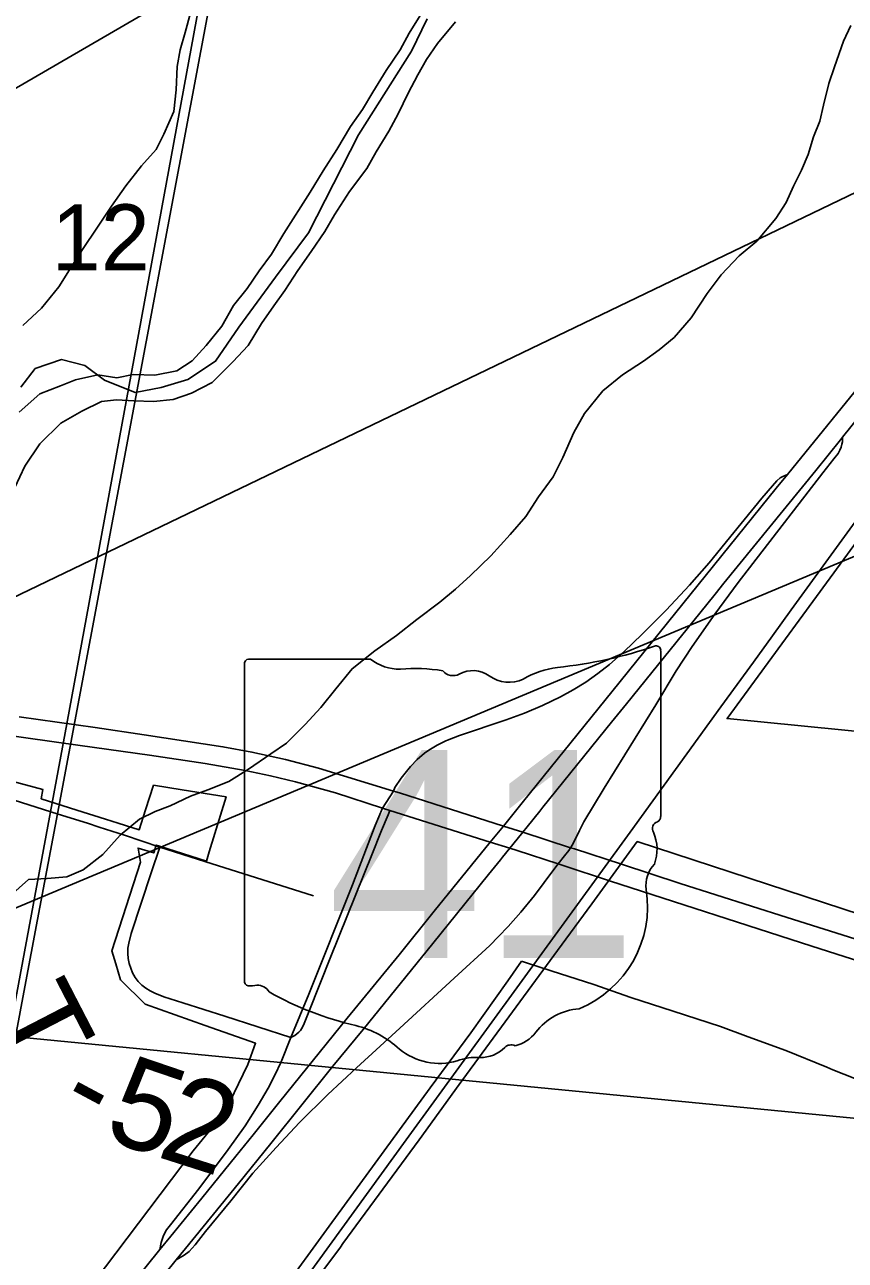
# Model space of a CAD drawing. Extents: x 0 to 34, y 0 to 22.
# Drawn here: x 7.664 to 8.184, y 18.991 to 19.774 of the extents above; entities that cross this region are included whole.
import ezdxf

# ---------------------------------------------------------------- set-up
doc = ezdxf.new("R2010")
doc.units = 0
for name, color, linetype in [('GM_X_City_Street', 7, 'Continuous'), ('GM_X_Interchange_Ramps', 7, 'Continuous'), ('GM_X_Major_River', 7, 'Continuous'), ('GM_X_Minor_River', 7, 'Continuous'), ('GM_X_Rail_Line', 7, 'Continuous'), ('GM_X_Section', 7, 'Continuous'), ('GM_X_Section_Text', 7, 'Continuous'), ('GM_X_State_Location', 7, 'Continuous'), ('GM_X_State_Route', 7, 'Continuous'), ('GM_X_State_Shield', 7, 'Continuous'), ('GM_X_Township_Road', 7, 'Continuous'), ('GM_X_Township_Road_Text', 7, 'Continuous'), ('GM_X_US_Route', 7, 'Continuous'), ('SC_Shading1', 7, 'Continuous'), ('SH_Text', 7, 'Continuous')]:
    doc.layers.add(name, color=color, linetype=linetype)

msp = doc.modelspace()

# ---------------------------------------------------------------- linework, layer by layer
at = {"layer": 'GM_X_City_Street'}
for points in [[(7.91919, 19.77751), (7.90941, 19.75708), (7.87575, 19.70401), (7.84421, 19.6418), (7.8231, 19.61391), (7.79992, 19.58224), (7.78521, 19.56057), (7.76768, 19.54907), (7.75073, 19.54398), (7.73433, 19.54078), (7.71492, 19.54851), (7.70248, 19.55793), (7.68758, 19.5617), (7.671, 19.55586), (7.66195, 19.54417)], [(7.66195, 19.54417), (7.671, 19.55586), (7.68758, 19.5617), (7.70248, 19.55793), (7.71492, 19.54851), (7.73433, 19.54078), (7.75073, 19.54398), (7.76768, 19.54907), (7.78521, 19.56057), (7.79992, 19.58224), (7.8231, 19.61391), (7.84421, 19.6418), (7.87575, 19.70401), (7.90941, 19.75708), (7.91919, 19.77751)]]:
    msp.add_lwpolyline(points, dxfattribs=at)
at = {"layer": 'GM_X_Interchange_Ramps'}
for points in [[(8.01008, 19.25236), (8.01161, 19.25468), (8.01578, 19.26328), (8.01862, 19.26879), (8.03147, 19.29009), (8.06414, 19.34298), (8.07694, 19.36431), (8.08715, 19.37993), (8.10146, 19.4003), (8.11626, 19.42031), (8.16997, 19.48977), (8.17692, 19.49875), (8.17957, 19.50218), (8.18071, 19.50412), (8.1816, 19.50621), (8.18205, 19.50793), (8.1823, 19.50954), (8.18237, 19.51088), (8.18237, 19.51241)], [(8.14754, 19.48879), (8.14463, 19.48758), (8.14282, 19.48663), (8.14072, 19.48482), (8.13806, 19.48157), (8.13129, 19.47375), (8.11356, 19.45208), (8.09783, 19.4328), (8.08553, 19.41876), (8.07065, 19.40286), (8.05534, 19.38737), (8.04407, 19.37664), (8.03472, 19.36843), (8.0274, 19.36266), (8.01976, 19.35731), (8.01183, 19.35241), (8.00364, 19.34793), (7.99243, 19.34253), (7.98099, 19.33766), (7.96934, 19.3333), (7.93984, 19.32342), (7.93211, 19.32039)], [(7.93211, 19.32039), (7.93115, 19.32001), (7.92555, 19.3173), (7.92023, 19.31411), (7.91769, 19.31232), (7.91296, 19.3083), (7.90867, 19.3038), (7.90284, 19.29651), (7.8989, 19.2905), (7.89798, 19.28825)], [(7.89798, 19.28825), (7.89093, 19.2774), (7.88638, 19.26634), (7.87191, 19.22875), (7.84439, 19.15966), (7.83296, 19.13208), (7.82669, 19.11668), (7.82282, 19.10823), (7.81856, 19.09996), (7.81231, 19.08926), (7.80388, 19.07626), (7.79316, 19.06106), (7.77454, 19.03628), (7.75678, 19.01354), (7.75424, 19.0102), (7.75217, 19.00659), (7.75075, 19.00233), (7.75003, 18.99775)], [(7.83296, 19.13208), (7.83541, 19.13341), (7.8379, 19.13559), (7.839, 19.13661), (7.83968, 19.13752), (7.84086, 19.13989), (7.84427, 19.14848), (7.85835, 19.18345), (7.88413, 19.24791), (7.89036, 19.26333), (7.89451, 19.27311), (7.89559, 19.27588)], [(8.00232, 19.24205), (8.00638, 19.24715), (8.00897, 19.25067), (8.01008, 19.25236)], [(7.9644, 19.1961), (7.97049, 19.20239), (7.97856, 19.21153), (7.98717, 19.22216), (7.9996, 19.23863), (8.00232, 19.24205)], [(7.76037, 18.99132), (7.76537, 18.99429), (7.76845, 18.99663), (7.77228, 19.00078), (7.7744, 19.00354), (7.77896, 19.00918), (7.79491, 19.02872), (7.80894, 19.04615), (7.82361, 19.06252), (7.83838, 19.07836), (7.85634, 19.09611), (7.87441, 19.1129), (7.90194, 19.13798), (7.93637, 19.16976), (7.95899, 19.1905), (7.9644, 19.1961)]]:
    msp.add_lwpolyline(points, dxfattribs=at)
at = {"layer": 'GM_X_Major_River'}
for points in [[(7.93723, 19.77565), (7.9259, 19.76186), (7.91883, 19.75177), (7.91328, 19.74202), (7.90731, 19.73038), (7.90092, 19.71724), (7.89497, 19.70636), (7.88707, 19.69325), (7.88112, 19.68275), (7.87015, 19.66819), (7.86068, 19.65322), (7.85436, 19.64273), (7.84571, 19.63002), (7.83745, 19.61806), (7.82918, 19.60533), (7.82212, 19.59562), (7.81426, 19.58441), (7.80595, 19.57054), (7.79622, 19.56014), (7.783, 19.54715), (7.76994, 19.54024), (7.75846, 19.53633), (7.7459, 19.53511), (7.73338, 19.53541), (7.72239, 19.53605), (7.71288, 19.53514), (7.70059, 19.52897), (7.68712, 19.52131), (7.67391, 19.50832), (7.66446, 19.4941), (7.65806, 19.48057)], [(7.91494, 19.7796), (7.90784, 19.76837), (7.90227, 19.75786), (7.89323, 19.74478), (7.88493, 19.73092), (7.87822, 19.72006), (7.87075, 19.70922), (7.86205, 19.69461), (7.85338, 19.68113), (7.84509, 19.66765), (7.82852, 19.64145), (7.82062, 19.62833), (7.81278, 19.61788), (7.8053, 19.60666), (7.79669, 19.59584), (7.78917, 19.58272), (7.77938, 19.57042), (7.77042, 19.56075), (7.76079, 19.55452), (7.74668, 19.55181), (7.73302, 19.55214), (7.72273, 19.5501), (7.71063, 19.55191), (7.69651, 19.54882), (7.68693, 19.54487), (7.6739, 19.53986), (7.66073, 19.52839)]]:
    msp.add_lwpolyline(points, dxfattribs=at)
at = {"layer": 'GM_X_Minor_River'}
for points in [[(7.6631, 19.58329), (7.67491, 19.5942), (7.68598, 19.60778), (7.69479, 19.62175), (7.7013, 19.63195), (7.7101, 19.64479), (7.71928, 19.65876), (7.72846, 19.67159), (7.7384, 19.68442), (7.74755, 19.69459), (7.75255, 19.70442), (7.75871, 19.71879), (7.76033, 19.73244), (7.76082, 19.74724), (7.76279, 19.75785), (7.7659, 19.76883), (7.7694, 19.78132)], [(7.65499, 19.22164), (7.6668, 19.23218), (7.67853, 19.23285), (7.69103, 19.23389), (7.70128, 19.23837), (7.71384, 19.24815), (7.7249, 19.26021), (7.73708, 19.27037), (7.74696, 19.27523), (7.75644, 19.27895), (7.76935, 19.28493), (7.78035, 19.28902), (7.79363, 19.29424), (7.80618, 19.30211), (7.82025, 19.31187), (7.83014, 19.31863), (7.84196, 19.33031), (7.85188, 19.34124), (7.86142, 19.35293), (7.87174, 19.36576), (7.8862, 19.37704), (7.89989, 19.3868), (7.91283, 19.39695), (7.92729, 19.40785), (7.93719, 19.41612), (7.94672, 19.42478), (7.95967, 19.43721), (7.97188, 19.45078), (7.98181, 19.46209), (7.98985, 19.47455), (7.99903, 19.48738), (8.00517, 19.49948), (8.0121, 19.51537), (8.01901, 19.52746), (8.03046, 19.54179), (8.04303, 19.55194), (8.05633, 19.56057), (8.06622, 19.56771), (8.07574, 19.5756), (8.08643, 19.58805), (8.09676, 19.60353), (8.10555, 19.61522), (8.11699, 19.62728), (8.12804, 19.63668), (8.14025, 19.65101), (8.14676, 19.6612), (8.15138, 19.67141), (8.15637, 19.68162), (8.16061, 19.69146), (8.1641, 19.70281), (8.16796, 19.71265), (8.17031, 19.72287), (8.17382, 19.73651), (8.1773, 19.74711), (8.1831, 19.76338), (8.18772, 19.77321)]]:
    msp.add_lwpolyline(points, dxfattribs=at)
at = {"layer": 'GM_X_Rail_Line'}
for points in [[(6.73244, 20.89996), (6.73558, 20.8782), (6.75257, 20.79657), (6.77176, 20.75571), (6.80444, 20.71734), (6.86223, 20.67506), (6.95222, 20.62273), (7.03048, 20.58139), (7.06553, 20.56464), (7.11106, 20.54569), (7.15491, 20.53375), (7.23618, 20.51761), (7.31988, 20.49303), (7.43844, 20.46855), (7.51371, 20.44121), (7.57645, 20.41309), (7.62966, 20.37962), (7.74184, 20.29969), (7.79545, 20.24366), (7.83539, 20.15953), (7.83526, 20.12527), (7.81886, 20.02519), (7.69091, 19.33091), (7.62688, 18.9861)], [(7.62913, 18.97477), (7.63473, 19.00559), (7.64118, 19.04048), (7.65192, 19.09748), (7.66436, 19.16432), (7.67245, 19.20679), (7.68506, 19.27385), (7.8111, 19.94513), (7.85131, 20.15956), (7.87155, 20.26802), (7.91662, 20.50767), (7.92471, 20.55149), (7.93777, 20.62065), (7.96531, 20.76705), (7.9851, 20.87296), (7.99014, 20.89996)], [(7.67235, 18.74566), (7.7577, 18.86316), (7.81105, 18.93663), (7.81658, 18.9442), (7.90608, 19.06726), (8.04779, 19.26227), (8.10524, 19.34153), (8.12591, 19.36986), (8.13806, 19.38663), (8.14993, 19.40304), (8.32663, 19.64609), (8.45952, 19.82871), (8.76287, 20.24597), (8.77342, 20.26036), (8.81967, 20.3248), (8.84497, 20.35923), (8.9, 20.435)]]:
    msp.add_lwpolyline(points, dxfattribs=at)
at = {"layer": 'GM_X_Section'}
for points in [[(8.36301, 20.07599), (8.27199, 19.07297), (7.26758, 19.17046), (7.35437, 20.16973)], [(7.26758, 19.17046), (8.27199, 19.07297), (8.18593, 18.07293), (7.17505, 18.16824)]]:
    msp.add_lwpolyline(points, close=True, dxfattribs=at)
at = {"layer": 'GM_X_State_Route'}
for points in [[(8.14741, 19.20814), (8.07946, 19.2297), (8.04246, 19.24191), (8.01251, 19.25157), (8.01008, 19.25236), (7.97981, 19.26212), (7.96756, 19.26608), (7.92359, 19.28026), (7.90179, 19.28707), (7.89798, 19.28825), (7.85048, 19.30269), (7.82944, 19.30816), (7.80823, 19.31291), (7.78993, 19.31636), (7.74001, 19.32393), (7.70894, 19.32846), (7.66072, 19.33518)], [(8.00232, 19.24205), (7.97633, 19.25053), (7.97162, 19.25201), (7.95928, 19.25588), (7.89559, 19.27588), (7.89495, 19.27609), (7.89226, 19.27697), (7.89093, 19.2774), (7.86111, 19.28715), (7.83592, 19.29403), (7.81996, 19.2979), (7.80401, 19.30125), (7.77864, 19.30562), (7.74338, 19.31099), (7.69954, 19.31704), (7.64696, 19.32443)], [(8.25757, 19.15986), (8.2244, 19.17025), (8.16292, 19.19008), (8.03475, 19.23145), (8.00536, 19.24105), (8.00232, 19.24205)], [(8.19523, 19.19297), (8.19431, 19.19326), (8.14741, 19.20814)]]:
    msp.add_lwpolyline(points, dxfattribs=at)
at = {"layer": 'GM_X_State_Shield'}
for p, q in [((8.0672, 19.27218), (8.0672, 19.37686)), ((7.80353, 19.36846), (7.80353, 19.16834)), ((7.88334, 19.3719), (7.80613, 19.3719)), ((8.06717, 19.2722), (8.0672, 19.27218))]:
    msp.add_line(p, q, dxfattribs=at)
for centre, radius, start, end in [((7.97327, 19.64473), 0.27962, 275.84447, 288.90645), ((8.06427, 19.3773), 0.00294, 351.86209, 97.738), ((7.80655, 19.36888), 0.00305, 98.1301, 188.1301), ((7.90173, 19.39513), 0.02963, 231.61951, 271.11188), ((7.91155, 19.25955), 0.10636, 80.48669, 94.98827), ((8.00894, 19.31078), 0.05625, 97.34618, 120.76885), ((7.9357, 19.36992), 0.00855, 219.79206, 297.10237), ((7.94825, 19.34679), 0.01777, 54.46668, 119.14113), ((7.97119, 19.37852), 0.02138, 233.85621, 294.82819), ((8.06406, 19.27177), 0.00314, 289.60381, 7.73413), ((8.06652, 19.26449), 0.00454, 107.94398, 210.33697), ((8.03762, 19.25126), 0.02727, 340.03296, 23.64957), ((8.07771, 19.22837), 0.01984, 136.8065, 186.92959), ((7.98894, 19.21505), 0.06994, 292.30889, 8.98584), ((7.80658, 19.1679), 0.00308, 171.95839, 258.30661), ((7.80704, 19.18837), 0.02352, 267.33899, 280.60386), ((7.81186, 19.15679), 0.00848, 29.74838, 93.27175), ((7.91892, 19.33659), 0.20192, 240.41292, 257.1985), ((8.01843, 19.11215), 0.0383, 94.40312, 142.57675), ((7.85872, 19.07843), 0.06318, 47.18416, 75.83597), ((7.9699, 19.14894), 0.0226, 282.87319, 323.27711), ((7.92705, 19.1558), 0.04009, 230.70037, 286.29184), ((7.95314, 19.14081), 0.02136, 268.77702, 315.54927), ((7.97246, 19.12143), 0.00601, 65.75173, 132.64842), ((7.95021, 19.08661), 0.03294, 85.69512, 111.20995)]:
    msp.add_arc(centre, radius, start, end, dxfattribs=at)
at = {"layer": 'GM_X_Township_Road'}
for p, q in [((7.74988, 19.2528), (7.77853, 19.24371)), ((7.77853, 19.24371), (7.84728, 19.22189))]:
    msp.add_line(p, q, dxfattribs=at)
for points in [[(7.60282, 19.29955), (7.62949, 19.29124), (7.63014, 19.29104), (7.68557, 19.2737), (7.70407, 19.26788), (7.71158, 19.26547), (7.72751, 19.26037), (7.74988, 19.2528)], [(7.74988, 19.2528), (7.74439, 19.23636), (7.73184, 19.19791), (7.73022, 19.19178), (7.72974, 19.18862), (7.72959, 19.1854), (7.72984, 19.18218), (7.73048, 19.17903), (7.73145, 19.17596), (7.73269, 19.17301), (7.73423, 19.17019), (7.73492, 19.16926), (7.73619, 19.16756), (7.73857, 19.16535), (7.74115, 19.16343), (7.74385, 19.16175), (7.74666, 19.16026), (7.75252, 19.1579), (7.7644, 19.15401), (7.79117, 19.14566), (7.83296, 19.13208)], [(7.73743, 18.84886), (7.74203, 18.85399), (7.74559, 18.85839), (7.74937, 18.86385), (7.76795, 18.88948), (7.79906, 18.93205), (7.82617, 18.96987), (7.8571, 19.01256), (7.92124, 19.10016), (7.94694, 19.13516), (7.97039, 19.16797), (7.97904, 19.18043)], [(7.97904, 19.18043), (7.99246, 19.1761), (7.99394, 19.17562), (7.9978, 19.17437)], [(7.9978, 19.17437), (8.02481, 19.16564), (8.0484, 19.15747), (8.07512, 19.14887), (8.10504, 19.13907), (8.12273, 19.13262), (8.14647, 19.12381), (8.17244, 19.11329), (8.17626, 19.11171), (8.19711, 19.1033), (8.22325, 19.09242)]]:
    msp.add_lwpolyline(points, dxfattribs=at)
at = {"layer": 'GM_X_US_Route'}
msp.add_line((7.92283, 19.1917), (7.95814, 19.23534), dxfattribs=at)
for points in [[(8.18111, 19.51086), (8.18237, 19.51241), (8.20804, 19.54414), (8.23863, 19.58235), (8.27701, 19.63099), (8.30691, 19.67044), (8.36665, 19.75122)], [(8.14754, 19.48879), (8.20146, 19.55514)], [(8.10166, 19.41304), (8.10721, 19.41998), (8.1654, 19.49143), (8.18111, 19.51086)], [(7.75003, 18.99775), (7.75693, 19.00631), (7.77653, 19.03024), (7.79816, 19.05692), (7.80912, 19.07053), (7.82587, 19.0915), (7.86866, 19.14438), (7.90156, 19.18442), (7.92378, 19.21214), (7.95928, 19.25588), (7.96756, 19.26608), (7.9803, 19.28177), (8.03193, 19.34569), (8.14042, 19.48004), (8.14754, 19.48879)], [(8.08124, 19.38755), (8.08316, 19.38991), (8.10166, 19.41304)], [(8.03604, 19.33185), (8.04548, 19.34357), (8.08124, 19.38755)], [(7.99071, 19.27561), (7.99259, 19.27794), (8.03604, 19.33185)], [(7.97351, 19.25434), (7.97981, 19.26212), (7.98253, 19.2655), (7.99071, 19.27561)], [(7.96702, 19.24632), (7.97162, 19.25201), (7.97351, 19.25434)], [(7.95814, 19.23534), (7.96571, 19.24469), (7.96702, 19.24632)], [(7.67317, 18.88358), (7.68764, 18.90161), (7.72907, 18.95238), (7.76037, 18.99132), (7.76616, 18.99841), (7.7997, 19.03971), (7.82032, 19.06498), (7.85958, 19.11398), (7.87868, 19.13715), (7.92283, 19.1917)], [(7.56425, 18.76761), (7.56677, 18.77074), (7.59234, 18.80248), (7.61237, 18.82629), (7.63454, 18.85451), (7.64626, 18.86912), (7.67472, 18.90476), (7.71617, 18.95569), (7.75003, 18.99775)]]:
    msp.add_lwpolyline(points, dxfattribs=at)
at = {"layer": 'SC_Shading1'}
for points in [[(8.19183, 19.44689), (8.10931, 19.33413), (8.20509, 19.32476)], [(7.6383, 18.8849), (7.77113, 19.0604), (7.79114, 19.08481), (7.80573, 19.115), (7.81062, 19.12844), (7.77862, 19.13978), (7.74065, 19.15324), (7.72506, 19.16871), (7.72207, 19.17877), (7.71961, 19.18704), (7.73764, 19.24323), (7.73611, 19.25208), (7.74612, 19.24903), (7.74767, 19.25401), (7.74965, 19.25334), (7.77939, 19.2439), (7.78114, 19.2498), (7.79194, 19.28464), (7.76402, 19.28909), (7.74592, 19.29197), (7.74092, 19.27638), (7.73686, 19.26376), (7.7235, 19.26798), (7.7155, 19.2705), (7.69739, 19.27621), (7.67481, 19.28333), (7.67587, 19.28918), (7.67586, 19.28918), (7.5774, 19.31555)], [(8.19422, 19.20985), (8.05234, 19.25627), (8.0235, 19.21686), (8.00178, 19.18718), (7.99724, 19.18097), (7.99017, 19.1713), (7.93965, 19.10228), (7.91411, 19.0672), (7.86596, 19.00155), (7.86436, 18.99937), (7.85386, 18.98506)]]:
    msp.add_lwpolyline(points, dxfattribs=at)
at = {"layer": 'SH_Text'}
for points in [[(9.2218, 20.89411), (4.45803, 17.87452), (9.2218, 20.64169)], [(9.24529, 20.17502), (4.46592, 17.8756), (9.24529, 19.87959)]]:
    msp.add_lwpolyline(points, close=True, dxfattribs=at)

# ---------------------------------------------------------------- texts
at = {"layer": 'GM_X_Section_Text'}
msp.add_text('12', height=0.041856, rotation=0.00001, dxfattribs=at).set_placement((7.68137, 19.61807))
at = {"layer": 'GM_X_State_Location'}
for s, p in [('s', (7.93239, 19.25509)), ('r', (7.93238, 19.25509))]:
    msp.add_text(s, height=0.000189, dxfattribs=at).set_placement(p)
msp.add_text('41', height=0.000189, rotation=0.00001, dxfattribs=at).set_placement((7.8847, 19.24131))
at = {"layer": 'GM_X_State_Shield'}
msp.add_text('41', height=0.131836, dxfattribs=at).set_placement((7.85624, 19.18245))
at = {"layer": 'GM_X_Township_Road_Text'}
for s, rotation, p in [('T', 297.33511, (7.63811, 19.14729)), ('5', 341.17961, (7.71302, 19.06849)), ('2', 342.27869, (7.74702, 19.05691)), ('-', 331.8178, (7.68337, 19.08344))]:
    msp.add_text(s, height=0.05682, rotation=rotation, dxfattribs=at).set_placement(p)

doc.saveas('drawing.dxf')
